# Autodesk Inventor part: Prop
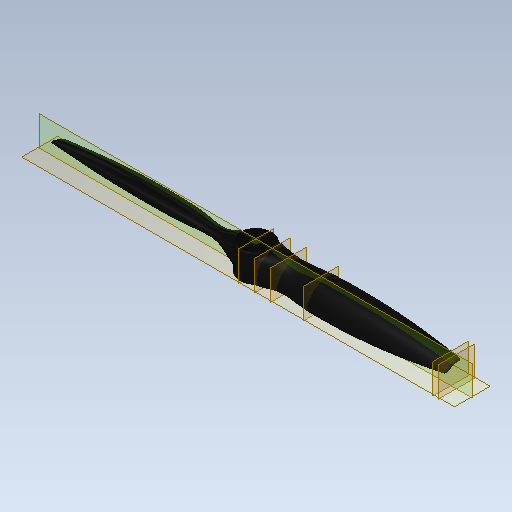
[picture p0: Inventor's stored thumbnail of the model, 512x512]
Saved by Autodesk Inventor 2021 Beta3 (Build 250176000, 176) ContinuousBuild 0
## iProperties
Created: 2013-05
Part Number: Prop
Material: ABS Plastic
Document SubType Name: Modeling
Designer: John
Density: 1 g/cm^3
Appearance: Glossy - Black
Author: John
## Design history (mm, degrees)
sketch "Sketch1"
  geometry: C1 r 9.525 at (0, 0); 1 further point
  constraints: 1 centre point, 1 coincident
  dimensions: "d0" = 19.05 diameter of C1
extrude "Extrusion1" new body sketch "Sketch1" distance "d1" = 15.875; taper "d2" = 0 deg
sketch "Sketch2"
  geometry: L1 (9.525, 15.875)-(9.525, 0) reference; L2 (9.525, 0)-(-9.525, 0) reference; L3 (-9.525, 0)-(-9.525, 15.875) reference; L4 (-9.525, 15.875)-(9.525, 15.875) reference; L5 (7.62, 15.557)-(-9.956, 15.558); L6 (-9.956, 15.558)-(-9.298, 16.697); L7 (-9.298, 16.697)-(-9.049, 1.257); L8 (-8.266, 0.476)-(11.467, 0.209); L9 (11.467, 0.209)-(8.935, -2.074); L10 (8.935, -2.074)-(9.207, 13.943); A1 r 1.587 centre (7.62, 13.97) between (9.207, 13.943) and (7.62, 15.557); A2 r 0.794 centre (-8.255, 1.27) between (-9.049, 1.257) and (-8.266, 0.476)
  constraints: 4 point on circle, 2 centre point, 2 tangent, 8 other
  dimensions: "d53" = 1.5875 diameter of A2; "d54" = 1.905 distance from line of L1 A1.centre; "d55" = 1.905 distance from line of L4 A1.centre (= d54); "d56" = 1.27 distance from line of L2 A2.centre; "d57" = 1.27 distance from line of L3 A2.centre; "d58" = 3.175 diameter of A1
  node "Project Cut Edges1"
workplane "Work Plane1"
sketch "Sketch3"
  geometry: L1 (0, 23.809)-(0, -31.728) reference; L2 (9.525, 15.875)-(-9.525, 15.875) reference; L3 (-9.525, 0)-(9.525, 0) reference; L4 (6.662, 14.257)-(-5.246, 16.641); L5 (-5.246, 16.641)-(-9.882, 11.396); L6 (-9.882, 11.396)-(-8.405, 1.784); L7 (7.923, 12.912)-(8.975, 5.091); L8 (8.975, 5.091)-(4.775, 0.613); L9 (4.775, 0.613)-(-7.652, 1.112); A1 r 1.587 centre (6.35, 12.7) between (7.923, 12.912) and (6.662, 14.257); A2 r 0.794 centre (-7.62, 1.905) between (-8.405, 1.784) and (-7.652, 1.112)
  constraints: 4 point on circle, 2 centre point, 2 tangent, 8 other
  dimensions: "d59" = 3.175 diameter of A1; "d60" = 1.5875 diameter of A2; "d61" = 1.905 horizontal distance of L3.start A2.centre (= d62); "d62" = 1.905 distance from line of L3 A2.centre; "d63" = 3.175 distance from line of L2 A1.centre; "d64" = 3.175 horizontal distance of L2.start A1.centre (= d63)
  node "Projected Loop1"
workplane "Work Plane2"
sketch "Sketch4"
  geometry: L1 (6.854, 12.814)-(5.964, 14.421); L2 (5.964, 14.421)-(-2.658, 13.618); L3 (-2.658, 13.618)-(-8.377, 3.483); L4 (-8.377, 3.483)-(-6.45, 1.519); L5 (-6.45, 1.519)-(-2.05, 5.082); L6 (-2.05, 5.082)-(2.919, 8.7); L7 (2.919, 8.7)-(6.087, 9.78); L8 (6.087, 9.78)-(7.471, 11.699); L9 (7.471, 11.699)-(6.854, 12.814)
  constraints: 1 collinear, 2 other
workplane "Work Plane3"
sketch "Sketch5"
  geometry: L1 (7.938, 13.299)-(8.826, 11.672); L2 (8.826, 11.672)-(6.704, 9.015); L3 (6.704, 9.015)-(2.898, 9.366); L4 (2.898, 9.366)-(-1.925, 6.863); L5 (-1.925, 6.863)-(-8.801, 0); L6 (-8.801, 0)-(-8.801, 6.257); L7 (-8.801, 6.257)-(-3.258, 14.466); L8 (-3.258, 14.466)-(6.704, 15.562); L9 (6.704, 15.562)-(7.938, 13.299); 1 further point
  constraints: 1 collinear, 2 other
workplane "Work Plane4"
sketch "Sketch6"
  geometry: L1 (5.033, 10.943)-(5.572, 10.107); L2 (5.572, 10.107)-(3.225, 10.462); L3 (3.225, 10.462)-(0.655, 9.4); L4 (0.655, 9.4)-(-2.376, 8.147); L5 (-2.376, 8.147)-(-4.164, 6.884); L6 (-4.164, 6.884)-(-4.435, 7.702); L7 (-4.435, 7.702)-(-0.838, 10.143); L8 (-0.838, 10.143)-(4.62, 11.582); L9 (4.62, 11.582)-(5.033, 10.943); 1 further point
  constraints: 1 collinear, 2 other
workplane "Work Plane5"
loft "Loft8" dims "d86" = 0, "d87" = 90 deg, "d88" = 0, "d89" = 90 deg, "d90" = 0, "d91" = 90 deg, "d92" = 0, "d93" = 90 deg, "d94" = 0, "d95" = 90 deg
delete_face "Delete Face1"
feature "Sculpt1"
fillet "Fillet3" dims "d98" = 0.79375
pattern_circular "Circular Pattern1" dims "d100" = 360 deg
sketch "Sketch8" dims "d103" = 1.905
  geometry: L1 (1.587, 7.453)-(1.587, 5.49); L2 (1.587, -5.49)-(1.588, -7.453); L3 (-1.588, 7.453)-(-1.588, 5.49); L4 (-1.587, -5.49)-(-1.587, -7.453); L5 (7.453, -1.587)-(5.49, -1.587); L6 (-5.49, -1.588)-(-7.453, -1.588); L7 (-7.453, 1.587)-(-5.49, 1.587); L8 (5.49, 1.588)-(7.453, 1.588); C1 r 9.525 at (0, 0) reference; 2 further points
  constraints: 16 end point, 8 parallel, 4 collinear, 2 coincident, 2 perpendicular, 2 vertical, 20 other
  dimensions: "d102" = 1.905 dimension on C1; "d104" = 3.175 distance between parallel lines of L1 L3; "d105" = 1.5875 distance from line of L1 C1.centre (derived); "d108" = 3.175 distance between parallel lines of L7 L6; "d109" = 1.5875 distance from line of point (0, 0) L7 (derived)
extrude "Extrusion2" cut sketch "Sketch8" distance "d110" = 13.335 (derived); taper "d111" = 0 deg
sketch "Sketch9"
  geometry: A1 r 5.715 centre (0, 0) between (5.49, 1.588) and (1.587, 5.49) reference
hole "Hole1" sketch "Sketch9" at (0, 0) diameter "d112" = 4.9784; stored, may be unused: countersink angle "d116" = 82 deg, drill point angle "d118" = 118 deg; dims "d113" = 19.05, "d114" = 12.8778, "d115" = 6.35, "d117" = 25.4
fillet "Fillet4" dims "d119" = 0.79375
body "Solid1"
body "Srf1"
patch "Boundary Patch1" dims "d96" = 10, "d97" = 0
other parameters: "d8" = 9.525, "d9" = 9.525, "d44" = 19.05, "d74" = 76.2, "d85" = 3.175, "d106" = 3.175, "d107" = 1.5875 (derived)
